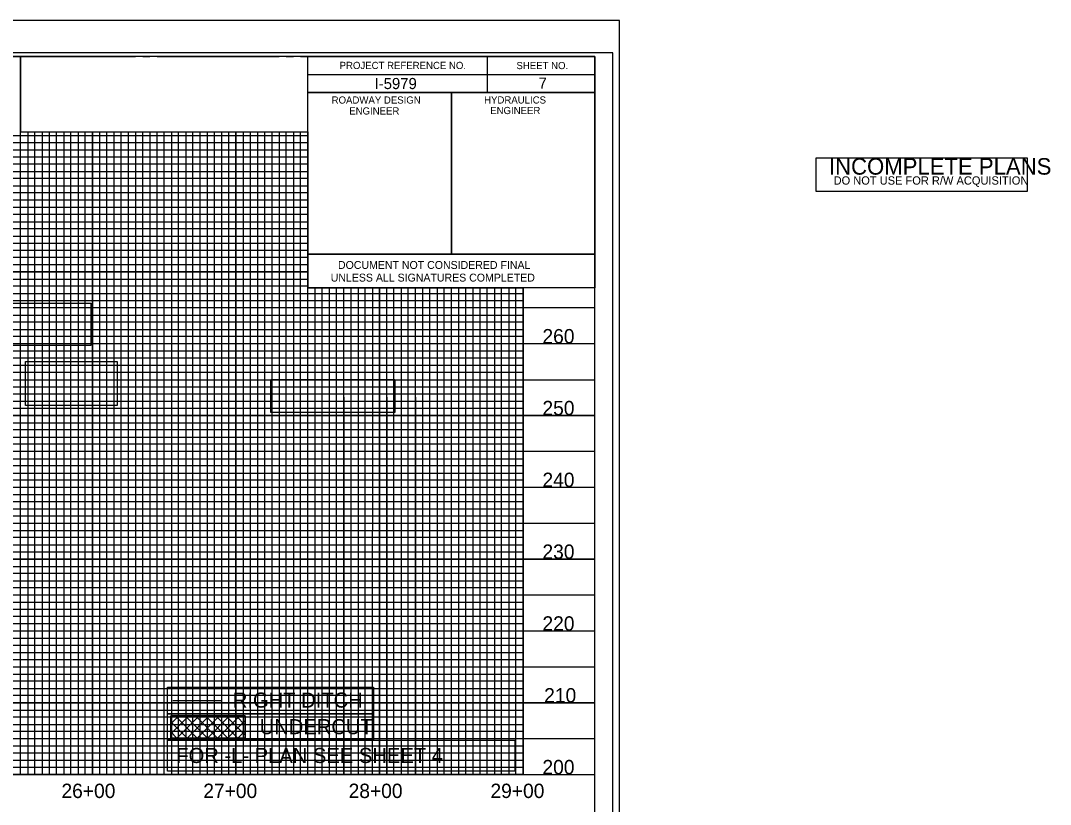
# Model space of a CAD drawing. Extents: x 1810963 to 1812948, y 722070 to 723250.
# Drawn here: x 1812230 to 1812948, y 722624 to 723170 of the extents above; entities that cross this region are included whole.
import ezdxf

# ---------------------------------------------------------------- set-up
doc = ezdxf.new("R2010")
doc.units = 0
for name, color, linetype in [('Exist Vertical Profile Horizontal Axis Label Major', 7, 'Continuous'), ('Exist Vertical Profile Vertical Axis Label', 7, 'Continuous'), ('Prop Grid Mask', 7, 'Continuous'), ('Prop Horizontal Alignment Station Label', 7, 'Continuous'), ('Prop Vertical Profile Ditch Grade Right', 7, 'Continuous'), ('Scratch_Level_3', 7, 'Continuous'), ('Sheet Cutting Line CELL', 7, 'Continuous'), ('Sheet Data Field CELL', 7, 'Continuous'), ('Sheet DOT Grid CELL', 7, 'Continuous'), ('Sheet Layout Profile Border Port 1', 7, 'Continuous'), ('Sheet Plot Border Inside CELL', 7, 'Continuous'), ('Sheet Plot Border Outside CELL', 7, 'Continuous'), ('Sheet Profile CELL', 7, 'Continuous'), ('Sheet Profile Grid Major CELL', 7, 'Continuous'), ('Sheet Profile Grid Middle CELL', 7, 'Continuous'), ('Sheet Profile Grid Minor CELL', 7, 'Continuous'), ('Sheet Sticker Exception Certification CELL', 7, 'Continuous'), ('Sheet Sticker Incomplete CELL', 7, 'Continuous')]:
    doc.layers.add(name, color=color, linetype=linetype)

msp = doc.modelspace()

# ---------------------------------------------------------------- linework, layer by layer
at = {"layer": 'Prop Grid Mask'}
for points in [[(1812200.84, 722973.14), (1812279.39, 722973.14), (1812279.39, 722943.7), (1812200.84, 722943.7)], [(1812233.85, 722932.55), (1812297.61, 722932.55), (1812297.61, 722901.85), (1812233.85, 722901.85)], [(1812404.62, 722919.94), (1812491.16, 722919.94), (1812491.16, 722896.95), (1812404.62, 722896.95)], [(1812332.66, 722705.78), (1812476.33, 722705.78), (1812476.33, 722687.29), (1812332.66, 722687.29)], [(1812332.66, 722687.29), (1812476.33, 722687.29), (1812476.33, 722668.81), (1812332.66, 722668.81)], [(1812332.66, 722668.81), (1812574.68, 722668.81), (1812574.68, 722647.28), (1812332.66, 722647.28)]]:
    msp.add_lwpolyline(points, close=True, dxfattribs=at)
at = {"layer": 'Prop Vertical Profile Ditch Grade Right'}
for p, q in [((1812336.57, 722696.47), (1812370.21, 722696.47)), ((1812335.11, 722673.22), (1812347.67, 722685.78)), ((1812335.11, 722680.29), (1812340.6, 722685.78)), ((1812386.81, 722685.78), (1812335.11, 722685.78)), ((1812335.11, 722685.78), (1812335.11, 722670.34)), ((1812335.11, 722681.65), (1812346.42, 722670.34)), ((1812338.05, 722685.78), (1812353.49, 722670.34)), ((1812339.3, 722670.34), (1812354.74, 722685.78)), ((1812345.12, 722685.78), (1812360.56, 722670.34)), ((1812346.37, 722670.34), (1812361.81, 722685.78)), ((1812352.19, 722685.78), (1812367.64, 722670.34)), ((1812353.44, 722670.34), (1812368.88, 722685.78)), ((1812359.27, 722685.78), (1812374.71, 722670.34)), ((1812360.51, 722670.34), (1812375.95, 722685.78)), ((1812366.34, 722685.78), (1812381.78, 722670.34)), ((1812367.58, 722670.34), (1812383.02, 722685.78)), ((1812373.41, 722685.78), (1812386.81, 722672.37)), ((1812374.65, 722670.34), (1812386.81, 722682.5)), ((1812380.48, 722685.78), (1812386.81, 722679.44)), ((1812386.81, 722670.34), (1812386.81, 722685.78)), ((1812335.11, 722674.58), (1812339.35, 722670.34)), ((1812381.72, 722670.34), (1812386.81, 722675.43)), ((1812335.11, 722670.34), (1812386.81, 722670.34))]:
    msp.add_line(p, q, dxfattribs=at)
msp.add_lwpolyline([(1812335.11, 722685.78), (1812386.81, 722685.78), (1812386.81, 722670.34), (1812335.11, 722670.34)], close=True, dxfattribs=at)
at = {"layer": 'Scratch_Level_3'}
msp.add_lwpolyline([(1811180.46, 723144.88), (1812230.46, 723144.88), (1812230.46, 723092.45), (1812430.5, 723092.45), (1812430.41, 722983.83), (1812580.46, 722983.83), (1812580.46, 722644.88), (1811180.46, 722644.88)], close=True, dxfattribs=at)
at = {"layer": 'Sheet Cutting Line CELL'}
msp.add_line((1812647.46, 723169.88), (1810963.46, 723169.88), dxfattribs=at)
at = {"layer": 'Sheet DOT Grid CELL'}
for p, q in [((1812230.46, 722644.88), (1812230.46, 723144.88)), ((1812280.46, 722644.88), (1812280.46, 723092.45)), ((1812330.46, 722644.88), (1812330.46, 723092.45)), ((1812380.46, 722644.88), (1812380.46, 723092.45)), ((1812430.41, 723044.88), (1811130.46, 723044.88)), ((1812430.46, 722644.88), (1812430.46, 723007.33)), ((1812430.46, 722994.88), (1811130.46, 722994.88)), ((1812480.46, 722644.88), (1812480.46, 722983.83)), ((1812530.46, 722644.88), (1812530.46, 722983.83)), ((1812580.46, 722644.88), (1812580.46, 722983.83)), ((1812630.46, 722944.88), (1811130.46, 722944.88)), ((1812630.46, 722894.88), (1811130.46, 722894.88)), ((1812630.46, 722844.88), (1811130.46, 722844.88)), ((1812630.46, 722794.88), (1811130.46, 722794.88)), ((1812630.46, 722744.88), (1811130.46, 722744.88)), ((1812630.46, 722694.88), (1811130.46, 722694.88))]:
    msp.add_line(p, q, dxfattribs=at)
at = {"layer": 'Sheet Layout Profile Border Port 1'}
msp.add_lwpolyline([(1811180.46, 722983.83), (1811180.46, 722644.88), (1812580.46, 722644.88), (1812580.46, 722983.83)], dxfattribs=at)
at = {"layer": 'Sheet Plot Border Inside CELL'}
msp.add_lwpolyline([(1810976.46, 722092.33), (1812642.96, 722092.33), (1812642.96, 723147.43), (1810976.46, 723147.43)], close=True, dxfattribs=at)
at = {"layer": 'Sheet Plot Border Outside CELL'}
msp.add_lwpolyline([(1810963.46, 722069.88), (1812647.46, 722069.88), (1812647.46, 723169.88), (1810963.46, 723169.88)], close=True, dxfattribs=at)
at = {"layer": 'Sheet Profile CELL'}
for p, q in [((1812555.46, 723144.83), (1812555.46, 723119.83)), ((1812430.41, 723132.33), (1812630.46, 723132.33)), ((1812530.46, 723119.83), (1812530.46, 723007.38)), ((1811130.46, 722644.88), (1812630.46, 722644.88))]:
    msp.add_line(p, q, dxfattribs=at)
for points in [[(1812630.46, 723144.88), (1811130.46, 723144.88), (1811130.46, 722094.88), (1812630.46, 722094.88)], [(1812430.41, 723144.88), (1812630.46, 723144.88), (1812630.46, 723119.83), (1812430.41, 723119.83)], [(1812430.41, 723119.83), (1812530.46, 723119.83), (1812530.46, 723007.33), (1812430.41, 723007.33)], [(1812530.46, 723119.83), (1812630.46, 723119.83), (1812630.46, 723007.33), (1812530.46, 723007.33)]]:
    msp.add_lwpolyline(points, close=True, dxfattribs=at)
at = {"layer": 'Sheet Profile Grid Major CELL'}
for points in [[(1812180.46, 722644.88), (1812230.46, 722644.88), (1812230.46, 723144.88), (1812280.46, 723144.88)], [(1812330.46, 723144.88), (1812380.46, 723144.88)], [(1812380.46, 723092.45), (1812380.46, 722644.88), (1812430.46, 722644.88), (1812430.46, 723144.88), (1812456.76, 723144.88)], [(1812280.46, 723092.45), (1812280.46, 722644.88), (1812330.46, 722644.88), (1812330.46, 723092.45)], [(1812430.46, 723044.88), (1811130.46, 723044.88), (1811130.46, 722994.88), (1812430.46, 722994.88)], [(1812580.46, 722983.83), (1812580.46, 722644.88), (1812630.46, 722644.88), (1812630.46, 722994.88)], [(1812480.46, 722983.83), (1812480.46, 722644.88), (1812530.46, 722644.88), (1812530.46, 722644.88), (1812530.46, 722983.83)], [(1812630.46, 722944.88), (1811130.46, 722944.88), (1811130.46, 722894.88), (1812630.46, 722894.88)], [(1812630.46, 722844.88), (1811130.46, 722844.88), (1811130.46, 722794.88), (1812630.46, 722794.88)], [(1812630.46, 722744.88), (1811130.46, 722744.88), (1811130.46, 722744.88), (1811130.46, 722694.88), (1812630.46, 722694.88)]]:
    msp.add_lwpolyline(points, dxfattribs=at)
at = {"layer": 'Sheet Profile Grid Middle CELL'}
for p, q in [((1812255.46, 723144.88), (1812305.46, 723144.88)), ((1812355.46, 723144.88), (1812405.46, 723144.88)), ((1812255.46, 722644.88), (1812255.46, 723092.45)), ((1812305.46, 723092.45), (1812305.46, 722644.88)), ((1812355.46, 722644.88), (1812355.46, 723092.45)), ((1812405.46, 723092.45), (1812405.46, 722644.88)), ((1812455.46, 722644.88), (1812455.46, 722983.83)), ((1812205.46, 722644.88), (1812255.46, 722644.88)), ((1812305.46, 722644.88), (1812355.46, 722644.88)), ((1812405.46, 722644.88), (1812455.46, 722644.88))]:
    msp.add_line(p, q, dxfattribs=at)
for points in [[(1812430.46, 723069.88), (1811130.46, 723069.88), (1811130.46, 723019.88), (1812430.46, 723019.88)], [(1812455.46, 722907.68), (1812455.46, 722644.88), (1812505.46, 722644.88), (1812505.46, 722983.83)], [(1812505.46, 722907.68), (1812505.46, 722644.88), (1812555.46, 722644.88), (1812555.46, 722983.83)], [(1812630.46, 722969.88), (1811130.46, 722969.88), (1811130.46, 722919.88), (1812455.46, 722919.88)], [(1812455.46, 722919.88), (1812630.46, 722919.88)], [(1812630.46, 722869.88), (1811130.46, 722869.88), (1811130.46, 722819.88), (1812630.46, 722819.88)], [(1812630.46, 722769.88), (1811130.46, 722769.88), (1811130.46, 722719.88), (1812630.46, 722719.88)], [(1812630.46, 722669.88), (1811130.46, 722669.88)]]:
    msp.add_lwpolyline(points, dxfattribs=at)
at = {"layer": 'Sheet Profile Grid Minor CELL'}
for p, q in [((1812225.46, 723144.88), (1812235.46, 723144.88)), ((1812240.46, 723144.88), (1812245.46, 723144.88)), ((1812250.46, 723144.88), (1812260.46, 723144.88)), ((1812265.46, 723144.88), (1812270.46, 723144.88)), ((1812275.46, 723144.88), (1812285.46, 723144.88)), ((1812290.46, 723144.88), (1812295.46, 723144.88)), ((1812300.46, 723144.88), (1812310.46, 723144.88)), ((1812315.46, 723144.88), (1812320.46, 723144.88)), ((1811180.46, 723089.88), (1812430.46, 723089.88)), ((1812235.46, 723092.45), (1812235.46, 722644.88)), ((1812240.46, 722644.88), (1812240.46, 723092.45)), ((1812245.46, 723092.45), (1812245.46, 722644.88)), ((1812250.46, 722644.88), (1812250.46, 723092.45)), ((1812260.46, 723092.45), (1812260.46, 722644.88)), ((1812265.46, 722644.88), (1812265.46, 723092.45)), ((1812270.46, 723092.45), (1812270.46, 722644.88)), ((1812275.46, 722644.88), (1812275.46, 723092.45)), ((1812285.46, 723092.45), (1812285.46, 722644.88)), ((1812290.46, 722644.88), (1812290.46, 723092.45)), ((1812295.46, 723092.45), (1812295.46, 722644.88)), ((1812300.46, 722644.88), (1812300.46, 723092.45)), ((1812310.46, 723092.45), (1812310.46, 722644.88)), ((1812315.46, 722644.88), (1812315.46, 723092.45)), ((1812320.46, 723092.45), (1812320.46, 722644.88)), ((1812430.41, 723009.88), (1811180.46, 723009.88)), ((1812430.46, 723004.88), (1811180.46, 723004.88)), ((1812430.46, 722999.88), (1811180.46, 722999.88)), ((1811180.46, 722989.88), (1812430.46, 722989.88)), ((1812430.46, 722984.88), (1811180.46, 722984.88)), ((1811180.46, 722979.88), (1812580.46, 722979.88)), ((1812580.46, 722959.88), (1811180.46, 722959.88)), ((1811180.46, 722954.88), (1812580.46, 722954.88)), ((1812580.46, 722934.88), (1811180.46, 722934.88)), ((1811180.46, 722929.88), (1812580.46, 722929.88)), ((1812580.46, 722909.88), (1811180.46, 722909.88)), ((1811180.46, 722904.88), (1812580.46, 722904.88)), ((1812580.46, 722899.88), (1811180.46, 722899.88)), ((1811180.46, 722889.88), (1812580.46, 722889.88)), ((1812580.46, 722884.88), (1811180.46, 722884.88)), ((1811180.46, 722879.88), (1812580.46, 722879.88)), ((1812580.46, 722874.88), (1811180.46, 722874.88)), ((1811180.46, 722864.88), (1812580.46, 722864.88)), ((1812580.46, 722859.88), (1811180.46, 722859.88)), ((1811180.46, 722854.88), (1812580.46, 722854.88)), ((1812580.46, 722849.88), (1811180.46, 722849.88)), ((1811180.46, 722839.88), (1812580.46, 722839.88)), ((1812580.46, 722834.88), (1811180.46, 722834.88)), ((1811180.46, 722829.88), (1812580.46, 722829.88)), ((1812580.46, 722824.88), (1811180.46, 722824.88)), ((1811180.46, 722814.88), (1812580.46, 722814.88)), ((1812580.46, 722809.88), (1811180.46, 722809.88)), ((1811180.46, 722804.88), (1812580.46, 722804.88)), ((1812580.46, 722799.88), (1811180.46, 722799.88)), ((1811180.46, 722789.88), (1812580.46, 722789.88)), ((1812580.46, 722784.88), (1811180.46, 722784.88)), ((1811180.46, 722779.88), (1812580.46, 722779.88)), ((1812580.46, 722774.88), (1811180.46, 722774.88)), ((1811180.46, 722764.88), (1812580.46, 722764.88)), ((1812580.46, 722759.88), (1811180.46, 722759.88)), ((1812580.46, 722754.88), (1811180.46, 722754.88)), ((1812580.46, 722749.88), (1811180.46, 722749.88)), ((1811180.46, 722739.88), (1812580.46, 722739.88)), ((1812580.46, 722734.88), (1811180.46, 722734.88)), ((1811180.46, 722729.88), (1812580.46, 722729.88)), ((1812580.46, 722724.88), (1811180.46, 722724.88)), ((1811180.46, 722714.88), (1812580.46, 722714.88)), ((1812580.46, 722709.88), (1811180.46, 722709.88)), ((1811180.46, 722704.88), (1812580.46, 722704.88)), ((1812580.46, 722699.88), (1811180.46, 722699.88)), ((1811180.46, 722689.88), (1812580.46, 722689.88)), ((1812580.46, 722684.88), (1811180.46, 722684.88)), ((1811180.46, 722679.88), (1812580.46, 722679.88)), ((1812580.46, 722674.88), (1811180.46, 722674.88)), ((1811180.46, 722664.88), (1812580.46, 722664.88)), ((1812580.46, 722659.88), (1811180.46, 722659.88)), ((1811180.46, 722654.88), (1812580.46, 722654.88)), ((1812235.46, 722644.88), (1812240.46, 722644.88)), ((1812245.46, 722644.88), (1812250.46, 722644.88)), ((1812260.46, 722644.88), (1812265.46, 722644.88)), ((1812270.46, 722644.88), (1812275.46, 722644.88)), ((1812285.46, 722644.88), (1812290.46, 722644.88)), ((1812295.46, 722644.88), (1812300.46, 722644.88)), ((1812310.46, 722644.88), (1812315.46, 722644.88))]:
    msp.add_line(p, q, dxfattribs=at)
for points in [[(1812325.46, 723144.88), (1812335.46, 723144.88)], [(1812340.46, 723144.88), (1812345.46, 723144.88)], [(1812350.46, 723144.88), (1812360.46, 723144.88)], [(1812365.46, 723144.88), (1812370.46, 723144.88)], [(1812375.46, 723144.88), (1812385.46, 723144.88)], [(1812390.46, 723144.88), (1812395.46, 723144.88)], [(1812400.46, 723144.88), (1812410.46, 723144.88)], [(1812415.46, 723144.88), (1812420.46, 723144.88)], [(1812425.46, 723144.88), (1812435.46, 723144.88)], [(1812320.46, 722644.88), (1812325.46, 722644.88), (1812325.46, 723092.45)], [(1812335.46, 723092.45), (1812335.46, 722644.88), (1812340.46, 722644.88), (1812340.46, 723092.45)], [(1812345.46, 723092.45), (1812345.46, 722644.88), (1812350.46, 722644.88), (1812350.46, 723092.45)], [(1812360.46, 723092.45), (1812360.46, 722644.88), (1812365.46, 722644.88), (1812365.46, 723092.45)], [(1812370.46, 723092.45), (1812370.46, 722644.88), (1812375.46, 722644.88), (1812375.46, 723092.45)], [(1812385.46, 723092.45), (1812385.46, 722644.88), (1812390.46, 722644.88), (1812390.46, 723092.45)], [(1812395.46, 723092.45), (1812395.46, 722644.88), (1812400.46, 722644.88), (1812400.46, 723092.45)], [(1812410.46, 723092.45), (1812410.46, 722644.88), (1812415.46, 722644.88), (1812415.46, 723092.45)], [(1812420.46, 723092.45), (1812420.46, 722644.88), (1812425.46, 722644.88), (1812425.46, 723092.45)], [(1812430.46, 723084.88), (1811180.46, 723084.88), (1811180.46, 723079.88), (1812430.46, 723079.88)], [(1812430.46, 723074.88), (1811180.46, 723074.88), (1811180.46, 723064.88), (1812430.46, 723064.88)], [(1812430.46, 723059.88), (1811180.46, 723059.88), (1811180.46, 723054.88), (1812430.46, 723054.88)], [(1812430.46, 723049.88), (1811180.46, 723049.88), (1811180.46, 723039.88), (1812430.46, 723039.88)], [(1812430.46, 723034.78), (1811180.56, 723034.78), (1811180.56, 723029.88), (1812430.46, 723029.88)], [(1812430.46, 723024.88), (1811180.46, 723024.88), (1811180.46, 723014.88), (1812430.46, 723014.88)], [(1812435.46, 722983.83), (1812435.46, 722644.88), (1812440.46, 722644.88), (1812440.46, 722983.83)], [(1812445.46, 722983.83), (1812445.46, 722644.88), (1812450.46, 722644.88), (1812450.46, 722983.83)], [(1812460.46, 722983.83), (1812460.46, 722644.88), (1812460.46, 722644.88), (1812465.46, 722644.88), (1812470.46, 722644.88), (1812470.46, 722983.83)], [(1812465.46, 722983.83), (1812465.46, 722644.88)], [(1812475.45, 722983.83), (1812475.36, 722644.93), (1812480.36, 722644.93), (1812485.46, 722644.88), (1812485.46, 722983.83)], [(1812485.46, 722907.68), (1812485.46, 722644.88), (1812490.46, 722644.88), (1812490.46, 722983.83)], [(1812495.46, 722983.83), (1812495.46, 722644.88), (1812500.46, 722644.88), (1812500.46, 722983.83)], [(1812510.46, 722983.83), (1812510.46, 722644.88), (1812515.46, 722644.88), (1812515.46, 722983.83)], [(1812520.46, 722983.83), (1812520.46, 722644.88), (1812525.46, 722644.88), (1812525.46, 722983.83)], [(1812535.46, 722983.83), (1812535.46, 722644.88), (1812540.46, 722644.88), (1812540.46, 722983.83)], [(1812545.46, 722983.83), (1812545.46, 722644.88), (1812550.46, 722644.88), (1812550.46, 722983.83)], [(1812560.46, 722983.83), (1812560.46, 722644.88), (1812565.46, 722644.88), (1812565.46, 722983.83)], [(1812570.46, 722983.83), (1812570.46, 722644.88), (1812575.46, 722644.88), (1812575.46, 722983.83)], [(1812580.46, 722974.88), (1811180.46, 722974.88), (1811180.46, 722964.88), (1812580.46, 722964.88)], [(1812580.46, 722949.88), (1811180.46, 722949.88), (1811180.46, 722939.88), (1812580.46, 722939.88)], [(1812580.46, 722924.88), (1811180.46, 722924.88), (1811180.46, 722914.88), (1812580.46, 722914.88)], [(1812580.46, 722649.88), (1811180.46, 722649.88)]]:
    msp.add_lwpolyline(points, dxfattribs=at)
at = {"layer": 'Sheet Sticker Exception Certification CELL'}
for p, q in [((1812430.41, 722983.83), (1812430.41, 723007.33)), ((1812430.41, 723007.33), (1812630.45, 723007.33)), ((1812430.41, 722983.83), (1812430.41, 723007.33)), ((1812430.41, 723007.33), (1812630.45, 723007.33)), ((1812630.45, 723007.32), (1812630.45, 722983.82)), ((1812630.45, 723007.32), (1812630.45, 722983.82)), ((1812630.45, 722983.83), (1812430.41, 722983.83)), ((1812630.45, 722983.83), (1812430.41, 722983.83))]:
    msp.add_line(p, q, dxfattribs=at)
at = {"layer": 'Sheet Sticker Incomplete CELL'}
msp.add_lwpolyline([(1812784.47, 723050.93), (1812784.47, 723074.43), (1812931.47, 723074.43), (1812931.47, 723050.93)], close=True, dxfattribs=at)

# ---------------------------------------------------------------- texts
at = {"layer": 'Exist Vertical Profile Horizontal Axis Label Major'}
for s, p in [('26+00', (1812258.9, 722628.6)), ('27+00', (1812357.68, 722628.6)), ('28+00', (1812458.9, 722628.6)), ('29+00', (1812557.68, 722628.6))]:
    msp.add_text(s, height=10, dxfattribs=at).set_placement(p)
at = {"layer": 'Exist Vertical Profile Vertical Axis Label'}
for s, p in [('260', (1812593.89, 722945.13)), ('250', (1812593.89, 722895.13)), ('240', (1812593.89, 722845.13)), ('230', (1812593.89, 722795.13)), ('220', (1812593.89, 722745.13)), ('210', (1812595.09, 722695.13)), ('200', (1812593.89, 722645.13))]:
    msp.add_text(s, height=10, dxfattribs=at).set_placement(p)
at = {"layer": 'Prop Horizontal Alignment Station Label'}
for s, p in [('RIGHT DITCH', (1812378.26, 722691.54)), ('UNDERCUT', (1812396.95, 722673.05)), ('FOR -L- PLAN SEE SHEET 4', (1812338.87, 722652.99))]:
    msp.add_text(s, height=10.5, rotation=360, dxfattribs=at).set_placement(p)
at = {"layer": 'Sheet Data Field CELL'}
for s, p in [('I-5979', (1812476.99, 723122.19)), ('7', (1812591.21, 723122.49))]:
    msp.add_text(s, height=7.75, dxfattribs=at).set_placement(p)
at = {"layer": 'Sheet Profile CELL'}
for s, height, p in [('PROJECT REFERENCE NO.', 5.0001, (1812452.62, 723136.19)), ('SHEET NO.', 5, (1812575.77, 723136.09)), ('ROADWAY DESIGN', 5.0001, (1812447.07, 723112.09)), ('HYDRAULICS', 5, (1812553.27, 723112.14)), ('ENGINEER', 5, (1812459.32, 723104.49)), ('ENGINEER', 5, (1812557.52, 723104.79))]:
    msp.add_text(s, height=height, dxfattribs=at).set_placement(p)
at = {"layer": 'Sheet Sticker Exception Certification CELL'}
for s, p in [('DOCUMENT NOT CONSIDERED FINAL', (1812451.48, 722996.99)), ('DOCUMENT NOT CONSIDERED FINAL', (1812451.48, 722996.99)), ('UNLESS ALL SIGNATURES COMPLETED', (1812446.41, 722988.19)), ('UNLESS ALL SIGNATURES COMPLETED', (1812446.41, 722988.19))]:
    msp.add_text(s, height=5.5, dxfattribs=at).set_placement(p)
at = {"layer": 'Sheet Sticker Incomplete CELL'}
for s, height, p in [('INCOMPLETE PLANS', 11.52, (1812793.42, 723062.63)), ('DO NOT USE FOR R/W ACQUISITION', 5.76, (1812796.67, 723055.68))]:
    msp.add_text(s, height=height, dxfattribs=at).set_placement(p)

doc.saveas('drawing.dxf')
